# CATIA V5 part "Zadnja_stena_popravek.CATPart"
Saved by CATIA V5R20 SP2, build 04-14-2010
Part number: Zadnja_stena_popravek
Bounding box of the stored display mesh (mm): x -23.1 to 23.1, y -17.5 to 17.5, z 0 to 6
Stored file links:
  C:\Documents and Settings\Administrator\My Documents\Hobi_dokumenti\CAD_CNC\Clap_CATIA\Zadnja_stena_popravek.CATPart
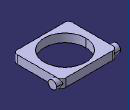
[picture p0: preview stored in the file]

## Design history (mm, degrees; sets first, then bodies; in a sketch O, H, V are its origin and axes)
Body1 (main body)
  Sketch1 on xy-plane, origin (0, 0, 0), H (1, 0, 0), V (0, 1, 0)
    point P1 (-20, 17.5)
    line L1 (-20, 17.5) -> (20, 17.5)
    line L2 (20, 17.5) -> (20, -17.5)
    line L3 (20, -17.5) -> (-20, -17.5)
    line L4 (-20, -17.5) -> (-20, 17.5)
    reference intersected line E2 through (0, 0) direction (0, 1) from yz-plane
    reference intersected line E3 through (0, 0) direction (-1, 0) from zx-plane
    circle A1 centre (0, 0) radius 15
    distance L1 L3 = 35
    distance L2 L4 = 40
    distance E3 L1 = 17.5
    distance P1 E2 = 20
    radius A1 = 15
    horizontal: L1 H, L3 H, E3 H
    vertical: L2 V, L4 V, E2 V
    perpendicularity: E2 L1
  Pad1: profile Sketch1, direction (0, 0, 1), length 6
  Sketch2 on face of Pad1 from Sketch1.L2, origin (20, 0, 0), H (0, 1, 0), V (0, 0, 1)
    circle A1 centre (14, 3) radius 3
    point P1 (14, 3)
    reference intersected line E1 through (0, 0) direction (-1, 0) from xy-plane
    reference intersected line E2 through (0, 0) direction (0, 1) from zx-plane
    distance P1 E1 = 3
    distance P1 E2 = 14
    radius A1 = 3
    vertical: E2 V
    horizontal: E1 H
  Pad2: profile Sketch2, direction (1, 0, 0), length 3.1
  Mirror1: of Pad2, Sketch2, about yz-plane
  Fillet1: radius 3, on edge [face of Pad1 from Sketch1.L4 | face of Pad1 from Sketch1.L1]; edge [face of Pad1 from Sketch1.L1 | face of Pad1 from Sketch1.L2]; edge [face of Pad1 from Sketch1.L3 | face of Pad1 from Sketch1.L4]; edge [face of Pad1 from Sketch1.L2 | face of Pad1 from Sketch1.L3]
